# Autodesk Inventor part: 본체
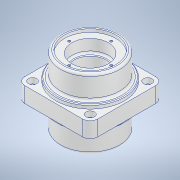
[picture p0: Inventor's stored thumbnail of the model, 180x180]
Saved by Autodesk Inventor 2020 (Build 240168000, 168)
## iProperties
Created: 2023-10
Part Number: 본체
Material: 알루미늄 6061
Document SubType Name: Modeling
Designer: oem
Density: 2.7 g/cm^3
Appearance: 알루미늄 - 평지
Mass: 947.344 g
Surface Area: 534.601 cm^2
Volume: 350.868 cm^3
Author: oem
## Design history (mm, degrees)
sketch "스케치2"
  geometry: L1 (-47, 47)-(47, 47); L2 (47, 47)-(47, -47); L3 (47, -47)-(-47, -47); L4 (-47, -47)-(-47, 47); L5 (-47, 47)-(47, -47); L6 (47, 47)-(-47, -47); 1 further point
  constraints: 12 end point, 2 midpoint, 2 parallel, 1 horizontal, 1 perpendicular
  dimensions: "d0" = 94 distance between parallel lines of L3 L1; "d1" = 94 distance between parallel lines of L4 L2
extrude "돌출1" new body sketch "스케치2" stored distance "d2" = 20; taper "d3" = 0 deg
sketch "스케치3"
  geometry: C1 r 44 at (0, 0); 1 further point
  constraints: 1 centre point, 1 coincident
  dimensions: "d4" = 88 diameter of C1
extrude "돌출2" join sketch "스케치3" distance "d5" = 5; taper "d6" = 0 deg
sketch "스케치4"
  geometry: C1 r 44 at (0, 0) reference; C2 r 38 at (0, 0)
  constraints: 1 centre point, 1 coincident
  dimensions: "d7" = 76 diameter of C2
extrude "돌출3" join sketch "스케치4" distance "d8" = 30; taper "d9" = 0 deg
sketch "스케치5"
  geometry: C1 r 38 at (0, 0) reference; C2 r 33 at (0, 0)
  constraints: 1 centre point, 1 coincident
  dimensions: "d10" = 66 diameter of C2
extrude "돌출4" cut sketch "스케치5" distance "d11" = 4; taper "d12" = 0 deg
sketch "스케치6"
  geometry: C1 r 33 at (0, 0) reference; C2 r 23.5 at (0, 0)
  constraints: 1 centre point, 1 coincident
  dimensions: "d13" = 47 diameter of C2
extrude "돌출5" cut sketch "스케치6" distance "d14" = 17; taper "d15" = 0 deg
sketch "스케치7"
  geometry: C1 r 23.5 at (0, 0) reference; C2 r 20.5 at (0, 0)
  constraints: 1 centre point, 1 coincident
  dimensions: "d16" = 41 diameter of C2
extrude "돌출6" cut sketch "스케치7" extent not by distance; stored distance "d17" = 17; taper "d18" = 0 deg
sketch "스케치8"
  geometry: C1 r 23.5 at (0, 0) reference; C2 r 23.5 at (0, 0) reference; C3 r 33 at (0, 0) reference; 4 further points
  constraints: 2 horizontal alignment, 2 vertical alignment
  dimensions: "d19" = 54 distance of point (27, 0) point (-27, 0); "d20" = 54 distance of point (0, -27) point (0, 27); "d21" = 27 distance of point (27, 0) C1.centre; "d22" = 27 distance of point (0, -27) C1.centre
hole "구멍1" sketch "스케치8" at (0, 27), (0, -27), (27, 0), (-27, 0) diameter "d23" = 3.242; stored, may be unused: countersink angle "d27" = 90 deg, drill point angle "d29" = 118 deg; dims "d24" = 8, "d25" = 4, "d26" = 2, "d28" = 10
sketch "스케치9"
  geometry: C1 r 7 at (47, -10); 1 further point
  constraints: 1 centre point, 1 coincident
  dimensions: "d30" = 14 diameter of C1
extrude "돌출7" cut sketch "스케치9" distance "d31" = 2; taper "d32" = 0 deg
sketch "스케치10"
  geometry: C1 r 7 at (0, 0) reference; C2 r 3.5 at (0, 0)
  constraints: 1 centre point, 1 coincident
  dimensions: "d33" = 7 diameter of C2
extrude "돌출8" cut sketch "스케치10" distance "d34" = 2; taper "d35" = 0 deg
sketch "스케치11"
  geometry: C1 r 3.5 at (0, 0) reference; 1 further point
  constraints: 1 coincident
hole "구멍2" sketch "스케치11" at (0, 0) diameter "d36" = 4.917; stored, may be unused: countersink angle "d40" = 90 deg, drill point angle "d42" = 118 deg; dims "d37" = 12, "d38" = 4, "d39" = 2, "d41" = 38
fillet "모깎기1" dims "d43" = 10
fillet "모깎기2" dims "d44" = 3
fillet "모깎기3" dims "d45" = 3
chamfer "모따기1" distance "d46" = 1; stored, may be unused: second distance "d47" = 2, angle "d48" = 45 deg
chamfer "모따기2" distance "d49" = 1; stored, may be unused: second distance "d50" = 2, angle "d51" = 45 deg
fillet "모깎기4" dims "d52" = 3
chamfer "모따기3" distance "d53" = 1; stored, may be unused: second distance "d54" = 2, angle "d55" = 45 deg
chamfer "모따기4" distance "d56" = 1; stored, may be unused: second distance "d57" = 2, angle "d58" = 45 deg
sketch "스케치14"
  geometry: C1 r 44 at (0, 0) reference; C2 r 53 at (0, 0); A1 r 10 centre (37, 37) between (47, 37) and (37, 47) reference; A2 r 10 centre (-37, 37) between (-37, 47) and (-47, 37) reference; A3 r 10 centre (-37, -37) between (-47, -37) and (-37, -47) reference; A4 r 10 centre (37, -37) between (37, -47) and (47, -37) reference; 4 further points
  constraints: 5 coincident, 1 centre point
  dimensions: "d59" = 106 diameter of C2
hole "구멍3" sketch "스케치14" at (37, -37), (-37, -37), (37, 37), (-37, 37) diameter "d60" = 11; stored, may be unused: countersink angle "d64" = 90 deg, drill point angle "d66" = 0 deg; dims "d61" = 12, "d62" = 4, "d63" = 2, "d65" = 7
sketch "스케치15"
  geometry: C1 r 5.5 at (0, 0) reference; C2 r 3.3 at (0, 0); 1 further point
  constraints: 1 centre point, 1 coincident
  dimensions: "d67" = 6.6 diameter of C2
extrude "돌출9" cut sketch "스케치15" extent not by distance; stored distance "d68" = 0; taper "d69" = 0 deg
sketch "스케치16"
  geometry: C1 r 5.5 at (0, 0) reference; C2 r 3.3 at (0, 0); 1 further point
  constraints: 1 centre point, 1 coincident
  dimensions: "d70" = 6.6 diameter of C2
extrude "돌출10" cut sketch "스케치16" extent not by distance; stored distance "d71" = 0; taper "d72" = 0 deg
sketch "스케치17"
  geometry: 2 further points
  constraints: 1 other
feature "엠보싱1" sketch "스케치17" dims "d0" = 94, "d1" = 94, "d73" = 0.5, "d74" = 0
node "솔리드1"
mirror "미러1"
mirror "미러2"
mirror "미러3"
mirror "미러4"
mirror "미러5"
mirror "미러6"
node "투영된 루프1"
feature "A9D066F2-1C7D-4E18-AEED-F7BC21143FA4" dims "d60" = 11, "d61" = 12, "d62" = 4, "d63" = 2, "d64" = 90 deg, "d65" = 7, "d66" = 0
